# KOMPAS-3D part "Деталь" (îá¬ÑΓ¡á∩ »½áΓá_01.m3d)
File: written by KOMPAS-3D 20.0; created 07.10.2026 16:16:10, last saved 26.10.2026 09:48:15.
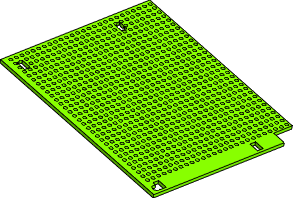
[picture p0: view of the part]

Document properties: Полное имя файла: D:\myProjects\Progect_esp32\box_compas\макетки\Макетная плата_01.m3d

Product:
- Part/product: Деталь
    Масса: 0.050617

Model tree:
1. Эскиз:1
2. Элемент выдавливания:1
     Расстояние 1 = 1.5
3. Эскиз:2  (with: Элемент выдавливания:1)
4. Элемент выдавливания:2
     Расстояние 2 = 1.5
5. Эскиз:3  (with: Элемент выдавливания:1)
6. Элемент выдавливания:3
     Расстояние 2 = 1.5
7. Массив по сетке:1  (with: Элемент выдавливания:3, Эскиз:3, Элемент выдавливания:1)  (806 pattern instances)
     Шаг 1 = 2.54; Угол раствора = -90; Шаг 2 = 2.54
8. Эскиз:5  (with: Элемент выдавливания:1)
9. Элемент выдавливания:5
     Расстояние 2 = 1.5
10. Эскиз:8  (with: Элемент выдавливания:1, Элемент выдавливания:2)
11. Элемент выдавливания:10
     Расстояние 1 = 1.5
12. Массив по сетке:2  (with: Элемент выдавливания:10, Эскиз:8)  (4 pattern instances)
     Шаг 1 = 75.9; Угол раствора = -90; Шаг 2 = 44.2
13. Элемент выдавливания:11  (with: Элемент выдавливания:1)
     Расстояние 2 = 0.5

Referenced files in D:\myProjects\Progect_esp32\box_compas\сборки компонентов\: ILI9341_86_50_DevBoard.a3d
